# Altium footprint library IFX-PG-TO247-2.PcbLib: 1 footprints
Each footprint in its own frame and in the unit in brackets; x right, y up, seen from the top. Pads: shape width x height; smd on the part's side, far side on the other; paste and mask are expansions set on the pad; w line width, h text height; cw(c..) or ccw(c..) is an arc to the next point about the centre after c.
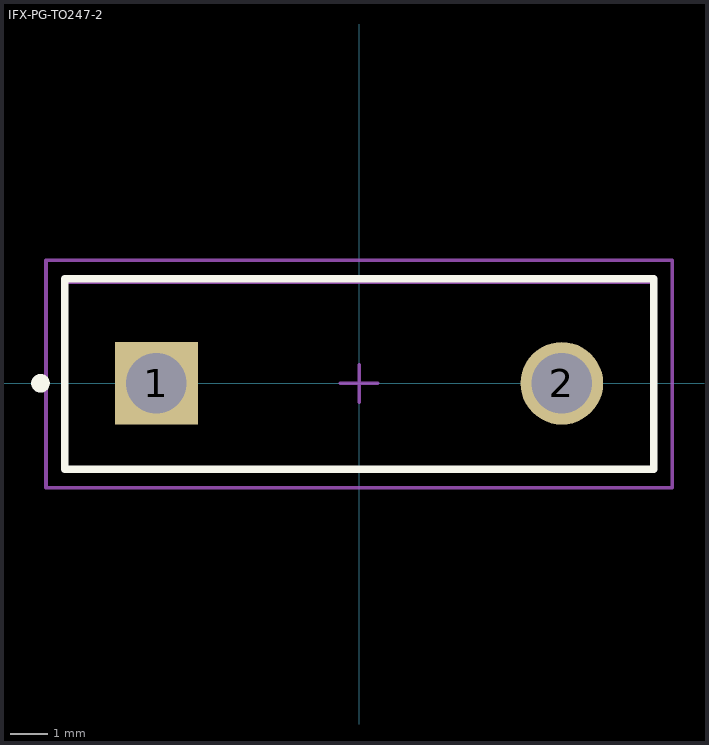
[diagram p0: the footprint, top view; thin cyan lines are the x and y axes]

## IFX-PG-TO247-2 [mm] "Diode; 10.88 mm pitch, 2 pin, 15.80 mm L X 5.00 mm W X 25.40 mm H body"
height 25.4
pads (2):
  rect 2.22x2.22 hole 1.62 paste+0 mask+0: 1(-5.44,0)
  round 2.22 hole 1.62 paste+0 mask+0: 2(5.44,0)
Top Overlay:
  circle w0.25: c-8.55,0 r0.125
  lines w0.2: -7.9,-2.3 7.9,-2.3 7.9,2.8 -7.9,2.8 -7.9,-2.3
M3 (ASY_Text_Top):
  text ".DESIGNATOR" at 0,0 h1.2
M13 (CMP_Body_OTL_Top):
  lines w0.1: -7.9,-2.29 7.9,-2.29 7.9,2.71 -7.9,2.71 -7.9,-2.29
  text "K" at -7.112,-0.22 h0.6
  text "A" at 6.731,-0.22 h0.6
M15 (CMP_Courtyard_Top):
  lines w0.1: -0.5,0 0.5,0 ; 0,-0.5 0,0.5 ; -8.4,-2.8 8.4,-2.8 8.4,3.3 -8.4,3.3 -8.4,-2.8
3D body "IDWD10G120C5.STEP": height 25.4, standoff -15.8, extent -7.9,-2.29 7.9,2.71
